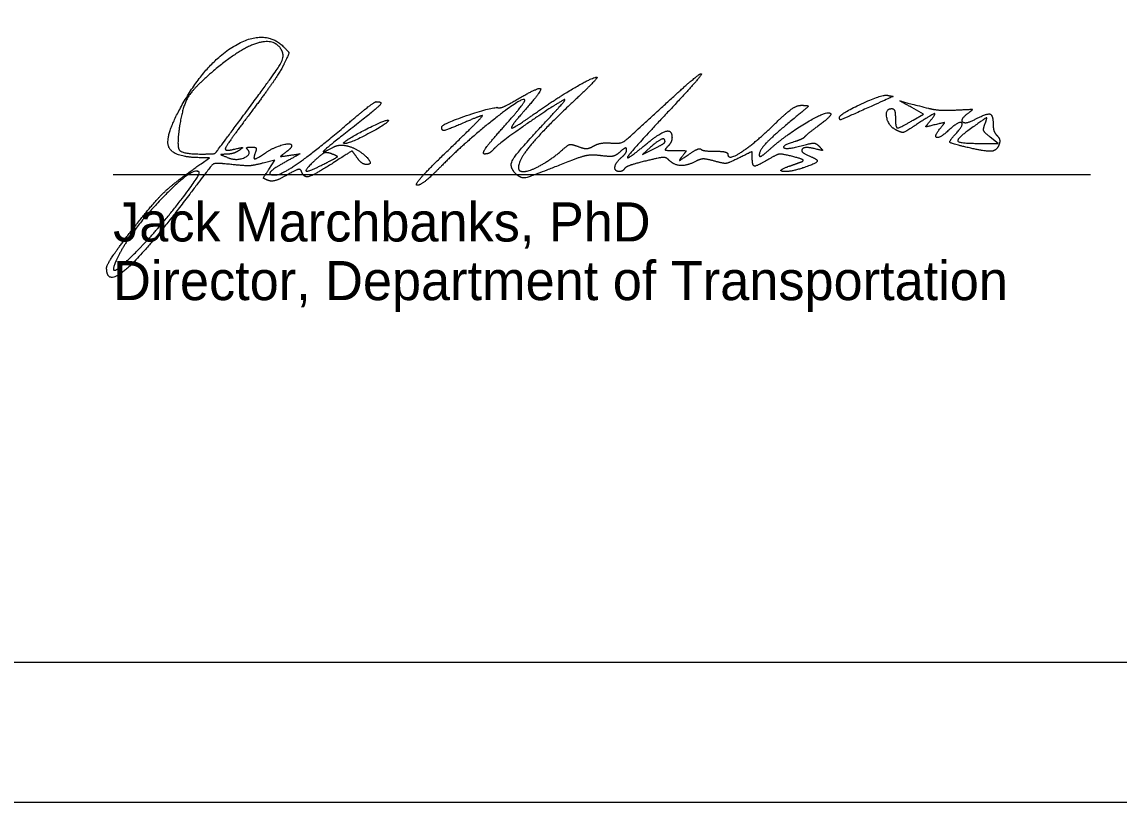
# Model space of a CAD drawing. Extents: x 0 to 34, y 0 to 22.
# Drawn here: x 26.081 to 30.011, y 0 to 2.792 of the extents above; entities that cross this region are included whole.
import ezdxf

# ---------------------------------------------------------------- set-up
doc = ezdxf.new("R2010")
doc.units = 0
for name, color, linetype in [('SH_Border', 7, 'Continuous'), ('SH_Cut_Line', 7, 'Continuous'), ('SH_Data', 7, 'Continuous'), ('SH_Text', 7, 'Continuous')]:
    doc.layers.add(name, color=color, linetype=linetype)

msp = doc.modelspace()

# ---------------------------------------------------------------- linework, layer by layer
at = {"layer": 'SH_Border'}
msp.add_lwpolyline([(1.5, 21.5), (33.5, 21.5), (33.5, 0.5), (1.5, 0.5)], close=True, dxfattribs=at)
at = {"layer": 'SH_Cut_Line'}
msp.add_lwpolyline([(0, 0), (34, 0), (34, 22), (0, 22)], close=True, dxfattribs=at)
at = {"layer": 'SH_Data'}
msp.add_line((26.408, 2.2466), (29.908, 2.2466), dxfattribs=at)
at = {"layer": 'SH_Text'}
for p, q in [((26.8703, 2.4516), (26.8703, 2.4516)), ((29.0096, 2.4508), (29.0096, 2.4508)), ((27.2356, 2.3618), (27.2356, 2.3618)), ((28.3846, 2.3638), (28.3846, 2.3638)), ((27.1909, 2.3201), (27.1909, 2.3201)), ((27.6075, 2.3327), (27.6075, 2.3327)), ((29.4621, 2.3445), (29.4621, 2.3445))]:
    msp.add_line(p, q, dxfattribs=at)
for points in [[(29.2734, 2.4412), (29.3098, 2.4627), (29.2691, 2.4857)], [(29.5221, 2.3577), (29.5784, 2.3578), (29.5496, 2.3799)], [(28.3329, 2.3441), (28.3034, 2.3185), (28.344, 2.3382)], [(26.7227, 2.2847), (26.7534, 2.3059), (26.7155, 2.3066)], [(26.9656, 2.2648), (26.9868, 2.2972), (26.9451, 2.2871)]]:
    msp.add_lwpolyline(points, dxfattribs=at)
for points in [[(26.659, 2.5024), (26.7453, 2.6528), (26.9534, 2.7688), (27.019, 2.7031)], [(27.0101, 2.6939), (26.9841, 2.736), (26.858, 2.6948), (26.7627, 2.6132)], [(26.8703, 2.4516), (26.9917, 2.6151), (27.0241, 2.6713), (27.0101, 2.6939)], [(27.019, 2.7031), (27.0378, 2.6844), (27.0379, 2.6793), (27.0195, 2.6409)], [(27.0195, 2.6409), (27.0086, 2.6179), (26.9569, 2.5423), (26.9046, 2.473)], [(26.7627, 2.6132), (26.696, 2.5561), (26.6572, 2.492), (26.6461, 2.4208)], [(27.9127, 2.4609), (27.9933, 2.5175), (28.1246, 2.5947), (28.1403, 2.5947)], [(28.1403, 2.5947), (28.1452, 2.5947), (28.1039, 2.5521), (28.0485, 2.5)], [(28.367, 2.4813), (28.442, 2.5504), (28.508, 2.607), (28.5138, 2.6071)], [(28.5138, 2.6071), (28.5195, 2.6071), (28.4675, 2.547), (28.3981, 2.4734)], [(27.8538, 2.5144), (27.9325, 2.5605), (27.9448, 2.5473), (27.8855, 2.48)], [(27.8819, 2.5141), (27.8722, 2.5237), (27.6625, 2.3568), (27.5846, 2.2775)], [(27.9569, 2.4347), (28.0031, 2.484), (28.0324, 2.5195), (28.0221, 2.5137)], [(29.0096, 2.4508), (29.0096, 2.4632), (29.1624, 2.5335), (29.1814, 2.5298)], [(29.1814, 2.5298), (29.202, 2.5258), (29.2028, 2.5262), (29.0811, 2.4715)], [(26.7155, 2.3066), (26.6176, 2.3083), (26.5942, 2.3894), (26.659, 2.5024)], [(27.2491, 2.4289), (27.2996, 2.4718), (27.3451, 2.5069), (27.3502, 2.507)], [(27.3502, 2.507), (27.3751, 2.5075), (27.3517, 2.482), (27.2659, 2.4147)], [(27.5848, 2.4166), (27.585, 2.4271), (27.7724, 2.4903), (27.7881, 2.4851)], [(28.0221, 2.5137), (27.9731, 2.4859), (27.7847, 2.3537), (27.7715, 2.3377)], [(27.7881, 2.4851), (27.7937, 2.4833), (27.8232, 2.4965), (27.8538, 2.5144)], [(27.804, 2.4138), (27.8503, 2.4655), (27.8853, 2.5106), (27.8819, 2.5141)], [(27.8855, 2.48), (27.8575, 2.4482), (27.8346, 2.4185), (27.8346, 2.414)], [(28.0485, 2.5), (27.9489, 2.4063), (27.8596, 2.2981), (27.8596, 2.2712)], [(28.192, 2.3589), (28.2255, 2.3561), (28.249, 2.3725), (28.367, 2.4813)], [(28.7752, 2.425), (28.8204, 2.4688), (28.8576, 2.4945), (28.8752, 2.4941)], [(28.8752, 2.4941), (28.8996, 2.4937), (28.8957, 2.4873), (28.8471, 2.4473)], [(29.2106, 2.4067), (29.1841, 2.4208), (29.1732, 2.4822), (29.1971, 2.4822)], [(29.1971, 2.4822), (29.204, 2.4822), (29.2096, 2.4681), (29.2096, 2.451)], [(29.2691, 2.4857), (29.2262, 2.5098), (29.2253, 2.5098), (29.3284, 2.4834)], [(29.3284, 2.4834), (29.349, 2.4781), (29.394, 2.4754), (29.4284, 2.4773)], [(29.4284, 2.4773), (29.4832, 2.4804), (29.4881, 2.4788), (29.4682, 2.464)], [(26.7242, 2.3197), (26.7709, 2.3197), (26.7754, 2.3238), (26.8703, 2.4516)], [(26.9046, 2.473), (26.8524, 2.4036), (26.8096, 2.343), (26.8096, 2.3382)], [(27.2356, 2.3618), (27.256, 2.3796), (27.3881, 2.4454), (27.3932, 2.4403)], [(27.3932, 2.4403), (27.3994, 2.4341), (27.2568, 2.3572), (27.2391, 2.3572)], [(27.6075, 2.3327), (27.6785, 2.4012), (27.7338, 2.4572), (27.7304, 2.4572)], [(27.7304, 2.4572), (27.727, 2.4572), (27.6979, 2.446), (27.6659, 2.4322)], [(27.8346, 2.414), (27.8346, 2.4096), (27.8698, 2.4307), (27.9127, 2.4609)], [(28.3981, 2.4734), (28.2686, 2.3358), (28.2365, 2.2886), (28.3187, 2.3563)], [(28.8471, 2.4473), (28.7731, 2.3863), (28.7221, 2.3328), (28.7221, 2.316)], [(28.7565, 2.3338), (28.8101, 2.3826), (28.9571, 2.4726), (28.9739, 2.467)], [(28.9739, 2.467), (28.9823, 2.4642), (28.9671, 2.4455), (28.94, 2.4253)], [(29.0811, 2.4715), (29.0186, 2.4434), (29.0096, 2.4408), (29.0096, 2.4508)], [(29.2096, 2.451), (29.2096, 2.4141), (29.2239, 2.412), (29.2734, 2.4412)], [(29.333, 2.4364), (29.3574, 2.466), (29.3416, 2.4622), (29.2854, 2.425)], [(29.3524, 2.4247), (29.3193, 2.4164), (29.3175, 2.4175), (29.333, 2.4364)], [(29.4682, 2.464), (29.4394, 2.4425), (29.4624, 2.4261), (29.496, 2.4441)], [(29.5299, 2.4254), (29.5398, 2.4512), (29.5316, 2.4481), (29.469, 2.4025)], [(29.496, 2.4441), (29.5363, 2.4657), (29.5596, 2.4599), (29.5596, 2.4285)], [(26.6461, 2.4208), (26.6347, 2.3474), (26.6561, 2.3197), (26.7242, 2.3197)], [(26.9878, 2.2447), (27.0109, 2.2447), (27.1369, 2.3335), (27.2491, 2.4289)], [(27.2659, 2.4147), (27.1726, 2.3417), (27.1512, 2.3201), (27.1951, 2.3436)], [(27.6659, 2.4322), (27.6033, 2.4054), (27.5845, 2.4018), (27.5848, 2.4166)], [(27.7382, 2.3197), (27.7279, 2.3197), (27.7568, 2.361), (27.804, 2.4138)], [(27.8498, 2.2491), (27.8246, 2.2743), (27.8535, 2.3244), (27.9569, 2.4347)], [(28.3187, 2.3563), (28.3671, 2.3962), (28.4096, 2.4066), (28.4096, 2.3785)], [(28.6096, 2.3182), (28.6096, 2.2954), (28.7049, 2.3568), (28.7752, 2.425)], [(28.94, 2.4253), (28.913, 2.4051), (28.888, 2.3851), (28.8846, 2.3808)], [(29.2854, 2.425), (29.2453, 2.3985), (29.232, 2.3952), (29.2106, 2.4067)], [(29.3725, 2.4139), (29.3871, 2.4315), (29.3848, 2.4328), (29.3524, 2.4247)], [(29.4012, 2.4052), (29.3693, 2.3752), (29.3462, 2.3823), (29.3725, 2.4139)], [(29.4264, 2.3925), (29.4569, 2.4262), (29.4352, 2.4371), (29.4012, 2.4052)], [(29.469, 2.4025), (29.4263, 2.3714), (29.4427, 2.3576), (29.5221, 2.3577)], [(29.5496, 2.3799), (29.5292, 2.3956), (29.5235, 2.4088), (29.5299, 2.4254)], [(29.5596, 2.4285), (29.5596, 2.4126), (29.566, 2.3933), (29.5738, 2.3856)], [(27.2391, 2.3572), (27.2344, 2.3572), (27.2328, 2.3593), (27.2356, 2.3618)], [(28.129, 2.3484), (28.1424, 2.356), (28.1708, 2.3607), (28.192, 2.3589)], [(28.3846, 2.3638), (28.3846, 2.3773), (28.3605, 2.3681), (28.3329, 2.3441)], [(28.344, 2.3382), (28.3663, 2.349), (28.3846, 2.3605), (28.3846, 2.3638)], [(28.4096, 2.3785), (28.4096, 2.3695), (28.4029, 2.3555), (28.3946, 2.3472)], [(28.8502, 2.3643), (28.8007, 2.3488), (28.8202, 2.3352), (28.872, 2.349)], [(28.8846, 2.3808), (28.8812, 2.3766), (28.8657, 2.3691), (28.8502, 2.3643)], [(28.872, 2.349), (28.9104, 2.3592), (28.9256, 2.3586), (28.9377, 2.3464)], [(29.4621, 2.3445), (29.4074, 2.3575), (29.4016, 2.3652), (29.4264, 2.3925)], [(29.5738, 2.3856), (29.5816, 2.3778), (29.5845, 2.3626), (29.5804, 2.3518)], [(26.8159, 2.3191), (26.7935, 2.3182), (26.7939, 2.3169), (26.82, 2.3064)], [(26.8096, 2.3382), (26.8096, 2.3334), (26.8251, 2.3331), (26.844, 2.3375)], [(26.8596, 2.3328), (26.8493, 2.3258), (26.8296, 2.3196), (26.8159, 2.3191)], [(26.82, 2.3064), (26.8499, 2.2945), (26.9061, 2.319), (26.8887, 2.3365)], [(26.844, 2.3375), (26.8695, 2.3434), (26.8735, 2.3422), (26.8596, 2.3328)], [(26.8887, 2.3365), (26.8842, 2.341), (26.8904, 2.3447), (26.9026, 2.3447)], [(26.9026, 2.3447), (26.9172, 2.3447), (26.9223, 2.3383), (26.9176, 2.326)], [(26.9176, 2.326), (26.9087, 2.3027), (26.9215, 2.302), (26.9537, 2.3241)], [(26.9537, 2.3241), (26.9826, 2.3439), (27.0471, 2.3614), (27.0471, 2.3495)], [(27.0255, 2.3254), (27.0066, 2.3116), (27.0086, 2.3103), (27.0411, 2.3152)], [(27.0471, 2.3495), (27.0471, 2.3449), (27.0374, 2.3341), (27.0255, 2.3254)], [(27.0411, 2.3152), (27.0779, 2.3208), (27.0778, 2.3205), (27.0323, 2.2954)], [(27.1909, 2.3201), (27.1736, 2.3265), (27.1571, 2.3213), (27.1377, 2.3036)], [(27.1627, 2.2838), (27.2091, 2.3075), (27.2127, 2.3121), (27.1909, 2.3201)], [(27.1951, 2.3436), (27.2077, 2.3504), (27.2316, 2.3525), (27.2482, 2.3483)], [(27.2812, 2.3069), (27.2644, 2.3309), (27.2624, 2.3305), (27.1966, 2.2881)], [(27.2482, 2.3483), (27.2843, 2.3391), (27.3427, 2.2822), (27.316, 2.2822)], [(27.4971, 2.2079), (27.4868, 2.2081), (27.5365, 2.2643), (27.6075, 2.3327)], [(27.7715, 2.3377), (27.7633, 2.3278), (27.7483, 2.3197), (27.7382, 2.3197)], [(27.8776, 2.2572), (27.8994, 2.2572), (27.9807, 2.3024), (28.0171, 2.3347)], [(28.0171, 2.3347), (28.0374, 2.3527), (28.0503, 2.3554), (28.074, 2.3464)], [(28.074, 2.3464), (28.0942, 2.3387), (28.113, 2.3394), (28.129, 2.3484)], [(28.2245, 2.3282), (28.2089, 2.314), (28.1876, 2.3096), (28.155, 2.3137)], [(28.2471, 2.3357), (28.2471, 2.3428), (28.237, 2.3394), (28.2245, 2.3282)], [(28.2284, 2.3072), (28.2387, 2.3158), (28.2471, 2.3286), (28.2471, 2.3357)], [(28.3946, 2.3472), (28.3829, 2.3355), (28.3888, 2.3322), (28.4211, 2.3322)], [(28.4211, 2.3322), (28.4587, 2.3322), (28.461, 2.3302), (28.4455, 2.3108)], [(28.4673, 2.3167), (28.4887, 2.3317), (28.5094, 2.3408), (28.5133, 2.3368)], [(28.5133, 2.3368), (28.5172, 2.3329), (28.5405, 2.3297), (28.565, 2.3297)], [(28.565, 2.3297), (28.5895, 2.3297), (28.6096, 2.3245), (28.6096, 2.3182)], [(28.6971, 2.3056), (28.6971, 2.3285), (28.696, 2.3285), (28.6499, 2.3057)], [(28.7221, 2.316), (28.7221, 2.3086), (28.7376, 2.3166), (28.7565, 2.3338)], [(28.8422, 2.3106), (28.8034, 2.3205), (28.7866, 2.3189), (28.759, 2.3026)], [(28.919, 2.3389), (28.8823, 2.348), (28.869, 2.3249), (28.9034, 2.3117)], [(28.9377, 2.3464), (28.9504, 2.3335), (28.9468, 2.3321), (28.919, 2.3389)], [(29.5804, 2.3518), (29.5723, 2.3307), (29.5311, 2.3282), (29.4621, 2.3445)], [(26.4717, 2.0425), (26.5494, 2.1429), (26.6295, 2.2202), (26.7227, 2.2847)], [(26.8039, 2.2848), (26.7705, 2.2881), (26.7587, 2.2776), (26.6821, 2.176)], [(26.9451, 2.2871), (26.9047, 2.2773), (26.8824, 2.277), (26.8039, 2.2848)], [(27.0323, 2.2954), (26.9812, 2.2672), (26.9615, 2.2447), (26.9878, 2.2447)], [(27.1966, 2.2881), (27.1277, 2.2438), (27.0903, 2.234), (27.0821, 2.2584)], [(27.1377, 2.3036), (27.0935, 2.2631), (27.1047, 2.2542), (27.1627, 2.2838)], [(27.316, 2.2822), (27.3064, 2.2822), (27.2908, 2.2933), (27.2812, 2.3069)], [(28.0495, 2.2966), (27.9034, 2.2389), (27.8684, 2.2306), (27.8498, 2.2491)], [(28.155, 2.3137), (28.1258, 2.3175), (28.086, 2.311), (28.0495, 2.2966)], [(28.2214, 2.2572), (28.203, 2.2572), (28.2076, 2.29), (28.2284, 2.3072)], [(28.3157, 2.2947), (28.2773, 2.2855), (28.2431, 2.2733), (28.2395, 2.2676)], [(28.4, 2.2968), (28.3889, 2.3079), (28.3688, 2.3074), (28.3157, 2.2947)], [(28.4963, 2.2943), (28.4656, 2.2778), (28.4177, 2.2791), (28.4, 2.2968)], [(28.4455, 2.3108), (28.4335, 2.2958), (28.44, 2.2976), (28.4673, 2.3167)], [(28.5608, 2.2944), (28.5339, 2.3021), (28.5108, 2.302), (28.4963, 2.2943)], [(28.6499, 2.3057), (28.6125, 2.2872), (28.594, 2.2849), (28.5608, 2.2944)], [(28.759, 2.3026), (28.714, 2.276), (28.6971, 2.2768), (28.6971, 2.3056)], [(28.8284, 2.2757), (28.8421, 2.2806), (28.8618, 2.2877), (28.8721, 2.2914)], [(28.8721, 2.2914), (28.8835, 2.2956), (28.8718, 2.3031), (28.8422, 2.3106)], [(28.9034, 2.3117), (28.9339, 2.3), (28.925, 2.2851), (28.8782, 2.2697)], [(26.7155, 2.2555), (26.6946, 2.2764), (26.4761, 2.0507), (26.4298, 1.9603)], [(26.4999, 1.9791), (26.5675, 2.0482), (26.7232, 2.2478), (26.7155, 2.2555)], [(26.9644, 2.2248), (26.9462, 2.2318), (26.9463, 2.2354), (26.9656, 2.2648)], [(27.031, 2.2446), (27.0054, 2.2295), (26.9754, 2.2206), (26.9644, 2.2248)], [(27.0821, 2.2584), (27.0793, 2.2669), (27.0601, 2.2618), (27.031, 2.2446)], [(27.5846, 2.2775), (27.5468, 2.239), (27.5074, 2.2077), (27.4971, 2.2079)], [(27.8596, 2.2712), (27.8596, 2.2635), (27.8677, 2.2572), (27.8776, 2.2572)], [(28.2395, 2.2676), (28.236, 2.2619), (28.2278, 2.2572), (28.2214, 2.2572)], [(28.8782, 2.2697), (28.8316, 2.2543), (28.7843, 2.26), (28.8284, 2.2757)], [(26.6821, 2.176), (26.5297, 1.9739), (26.3846, 1.8452), (26.3846, 1.9122)], [(26.3846, 1.9122), (26.3846, 1.9219), (26.4238, 1.9805), (26.4717, 2.0425)], [(26.4298, 1.9603), (26.3985, 1.8994), (26.4302, 1.9078), (26.4999, 1.9791)]]:
    msp.add_open_spline(points, degree=2, dxfattribs=at)

# ---------------------------------------------------------------- texts
for s, p in [('Jack Marchbanks, PhD', (26.408, 2.0066)), ('Director, Department of Transportation', (26.408, 1.7966))]:
    msp.add_text(s, height=0.14, dxfattribs=at).set_placement(p)

doc.saveas('drawing.dxf')
